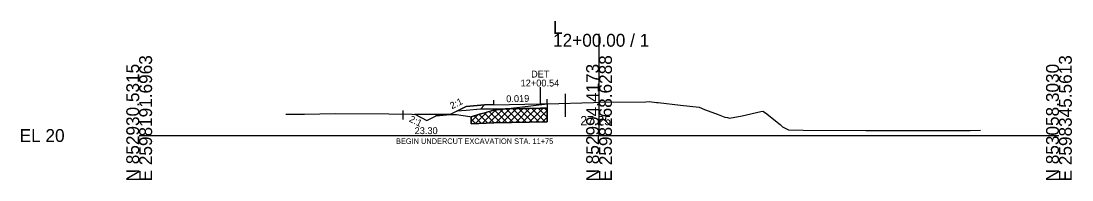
# Model space of a CAD drawing. Extents: x -26 to 1203, y -10 to 9526.
# Drawn here: x -25.7 to 202.8, y 1990.3 to 2024.9 of the extents above; entities that cross this region are included whole.
import ezdxf

# ---------------------------------------------------------------- set-up
doc = ezdxf.new("R2010")
doc.units = 0
for name, color, linetype in [('Exist Cross Section Cell', 7, 'Continuous'), ('Exist XS Center Line Elevation Label', 7, 'Continuous'), ('Exist XS Ground Line', 7, 'Continuous'), ('Prop XS Alignment Label', 7, 'Continuous'), ('Prop XS DDE', 7, 'Continuous'), ('Prop XS DDE Earthwork Shape', 7, 'Continuous'), ('Prop XS DDE Elevations', 7, 'Continuous'), ('Prop XS DDE Slope Text', 7, 'Continuous'), ('Prop XS Earthwork Shape', 7, 'Continuous'), ('Prop XS EOT Tick Mark', 7, 'Continuous'), ('Prop XS Exc Vertical Line 1', 7, 'Continuous'), ('Prop XS Exc Vertical Line 2', 7, 'Continuous'), ('Prop XS Finish Grade', 7, 'Continuous'), ('Prop XS Finish Grade Earthwork', 7, 'Continuous'), ('Prop XS Finish Grade Paved Shoulder', 7, 'Continuous'), ('Prop XS Finish Grade Pavement', 7, 'Continuous'), ('Prop XS Pvmt Edge Slope', 7, 'Continuous'), ('Prop XS SE Text', 7, 'Continuous'), ('Prop XS Side Slope Text', 7, 'Continuous'), ('Prop XS Station Labels', 7, 'Continuous'), ('Prop XS Subgrade Earthwork', 7, 'Continuous'), ('Prop XS Undercut Exc', 7, 'Continuous'), ('Prop XS Undercut Exc Hatch', 7, 'Continuous'), ('Scratch_Level_1', 7, 'Continuous')]:
    doc.layers.add(name, color=color, linetype=linetype)

msp = doc.modelspace()

# ---------------------------------------------------------------- linework, layer by layer
at = {"layer": 'Exist Cross Section Cell'}
for p, q in [((100, 2000), (100, 2022.14)), ((0, 2000), (100, 2000)), ((100, 2000), (200, 2000))]:
    msp.add_line(p, q, dxfattribs=at)
at = {"layer": 'Exist XS Ground Line'}
for p, q in [((82.76, 2006.18), (88.75, 2006.89)), ((88.75, 2006.89), (98.76, 2007.21)), ((98.76, 2007.21), (99.98, 2007.25)), ((99.98, 2007.25), (110.19, 2007.37)), ((110.19, 2007.37), (110.9, 2007.38)), ((110.9, 2007.38), (112.47, 2007.2)), ((112.47, 2007.2), (112.87, 2007.16)), ((112.87, 2007.16), (117.69, 2006.61)), ((117.69, 2006.61), (121.76, 2006.17)), ((31.91, 2004.63), (35.95, 2004.65)), ((35.95, 2004.65), (42.59, 2004.77)), ((42.59, 2004.77), (54.3, 2004.72)), ((54.3, 2004.72), (64.41, 2004.55)), ((64.41, 2004.55), (69.02, 2004.57)), ((69.02, 2004.57), (71.87, 2004.17)), ((72.18, 2004.08), (73.97, 2004.63)), ((73.97, 2004.63), (77.13, 2005.54)), ((77.13, 2005.54), (82.76, 2006.18)), ((121.76, 2006.17), (122.95, 2005.69)), ((122.95, 2005.69), (125.9, 2004.58)), ((125.9, 2004.58), (127.34, 2004)), ((128.39, 2003.8), (131.09, 2004.31)), ((131.09, 2004.31), (135.19, 2005.23)), ((135.19, 2005.23), (135.64, 2005.33)), ((135.64, 2005.33), (136.16, 2004.95)), ((136.16, 2004.95), (139.36, 2002.43)), ((71.87, 2004.17), (72.18, 2004.08)), ((127.34, 2004), (127.95, 2003.89)), ((127.95, 2003.89), (128.39, 2003.8)), ((139.36, 2002.43), (139.92, 2001.92)), ((139.92, 2001.92), (141.17, 2001.22)), ((141.17, 2001.22), (144.39, 2001.19)), ((144.39, 2001.19), (157.99, 2001.06)), ((157.99, 2001.06), (180.68, 2001.12)), ((180.68, 2001.12), (182.96, 2001.14))]:
    msp.add_line(p, q, dxfattribs=at)
at = {"layer": 'Prop XS DDE'}
for p, q in [((59.91, 2004.63), (62.56, 2003.3)), ((62.56, 2003.3), (64.59, 2004.31)), ((64.59, 2004.31), (67.59, 2004.56))]:
    msp.add_line(p, q, dxfattribs=at)
at = {"layer": 'Prop XS DDE Earthwork Shape'}
for p, q in [((64.41, 2004.55), (59.91, 2004.63)), ((59.91, 2004.63), (62.56, 2003.3)), ((62.56, 2003.3), (64.59, 2004.31)), ((67.59, 2004.56), (64.41, 2004.55)), ((64.59, 2004.31), (67.59, 2004.56))]:
    msp.add_line(p, q, dxfattribs=at)
at = {"layer": 'Prop XS Earthwork Shape'}
for points in [[(79.55, 2005.82), (82.76, 2006.18), (88.71, 2006.88), (88.71, 2005.99), (87.26, 2005.96)], [(67.59, 2004.56), (69.02, 2004.57), (71.87, 2004.17), (72.18, 2004.08), (73.97, 2004.63), (77.13, 2005.54), (79.55, 2005.82), (77.12, 2005.77), (75.12, 2005.73), (74.19, 2005.71), (71.12, 2005.47), (69.08, 2005.31)], [(87.26, 2005.96), (88.71, 2005.99), (88.71, 2002.99), (77.12, 2002.77), (72.18, 2002.55), (72.18, 2004.08), (73.97, 2004.63), (77.13, 2005.54), (79.55, 2005.82)]]:
    msp.add_lwpolyline(points, close=True, dxfattribs=at)
at = {"layer": 'Prop XS EOT Tick Mark'}
for p, q in [((77.12, 2006.69), (77.12, 2007.69)), ((88.71, 2006.91), (88.71, 2007.91))]:
    msp.add_line(p, q, dxfattribs=at)
at = {"layer": 'Prop XS Exc Vertical Line 1'}
msp.add_line((57.35, 2005.47), (57.35, 2003.47), dxfattribs=at)
at = {"layer": 'Prop XS Exc Vertical Line 2'}
msp.add_line((92.62, 2009.06), (92.62, 2004.07), dxfattribs=at)
at = {"layer": 'Prop XS Finish Grade'}
for p, q in [((75.12, 2006.65), (71.12, 2006.33)), ((71.12, 2006.33), (69.08, 2005.31))]:
    msp.add_line(p, q, dxfattribs=at)
at = {"layer": 'Prop XS Finish Grade Earthwork'}
msp.add_line((69.08, 2005.31), (67.59, 2004.56), dxfattribs=at)
at = {"layer": 'Prop XS Finish Grade Paved Shoulder'}
msp.add_line((77.12, 2006.69), (75.12, 2006.65), dxfattribs=at)
at = {"layer": 'Prop XS Finish Grade Pavement'}
for p, q in [((77.12, 2006.69), (87.26, 2006.88)), ((87.26, 2006.88), (88.71, 2006.91))]:
    msp.add_line(p, q, dxfattribs=at)
at = {"layer": 'Prop XS Pvmt Edge Slope'}
msp.add_line((75.12, 2006.65), (74.19, 2005.71), dxfattribs=at)
at = {"layer": 'Prop XS Side Slope Text'}
msp.add_line((87.26, 2006.88), (87.26, 2010.53), dxfattribs=at)
at = {"layer": 'Prop XS Subgrade Earthwork'}
for p, q in [((88.71, 2006.88), (88.71, 2005.99)), ((71.12, 2005.47), (69.08, 2005.31)), ((74.19, 2005.71), (71.12, 2005.47)), ((75.12, 2005.73), (74.19, 2005.71)), ((77.12, 2005.77), (75.12, 2005.73)), ((87.26, 2005.96), (77.12, 2005.77))]:
    msp.add_line(p, q, dxfattribs=at)
at = {"layer": 'Prop XS Undercut Exc'}
for p, q in [((79.55, 2005.82), (88.71, 2005.99)), ((88.71, 2005.99), (88.71, 2002.99)), ((72.18, 2002.55), (72.18, 2004.08)), ((77.12, 2002.77), (72.18, 2002.55)), ((88.71, 2002.99), (77.12, 2002.77))]:
    msp.add_line(p, q, dxfattribs=at)
at = {"layer": 'Prop XS Undercut Exc Hatch'}
for p, q in [((72.17, 2003.03), (73.68, 2004.54)), ((72.84, 2004.28), (74.47, 2002.65)), ((73.15, 2002.6), (75.67, 2005.12)), ((73.93, 2004.61), (75.83, 2002.71)), ((74.63, 2002.66), (77.56, 2005.59)), ((75.02, 2004.93), (77.18, 2002.77)), ((76.11, 2002.73), (79.15, 2005.77)), ((76.12, 2005.25), (78.57, 2002.8)), ((77.23, 2005.55), (79.96, 2002.82)), ((77.57, 2002.78), (80.63, 2005.84)), ((78.5, 2005.7), (81.34, 2002.85)), ((79.02, 2002.81), (82.08, 2005.86)), ((79.79, 2005.82), (82.73, 2002.88)), ((80.46, 2002.83), (83.52, 2005.89)), ((81.18, 2005.85), (84.12, 2002.9)), ((81.9, 2002.86), (84.96, 2005.92)), ((82.56, 2005.87), (85.51, 2002.93)), ((83.34, 2002.89), (86.4, 2005.95)), ((83.95, 2005.9), (86.89, 2002.96)), ((84.78, 2002.92), (87.84, 2005.98)), ((85.34, 2005.93), (88.28, 2002.98)), ((86.23, 2002.94), (88.71, 2005.43)), ((86.73, 2005.95), (88.71, 2003.97)), ((88.11, 2005.98), (88.71, 2005.38)), ((72.17, 2003.54), (73.12, 2002.59)), ((87.67, 2002.97), (88.71, 2004.02))]:
    msp.add_line(p, q, dxfattribs=at)
msp.add_lwpolyline([(72.18, 2002.55), (77.12, 2002.77), (88.71, 2002.99), (88.71, 2005.99), (79.55, 2005.82), (77.13, 2005.54), (74.93, 2004.9), (73.97, 2004.63), (72.18, 2004.08)], close=True, dxfattribs=at)
at = {"layer": 'Scratch_Level_1'}
msp.add_lwpolyline([(74.19, 2005.71), (71.12, 2005.47), (69.08, 2005.31), (71.12, 2006.33), (75.12, 2006.65)], close=True, dxfattribs=at)

# ---------------------------------------------------------------- texts
at = {"layer": 'Exist Cross Section Cell'}
for s, p in [('L', (90, 2022.14)), ('12+00.00 / 1', (90, 2019.34)), ('EL 20', (-26, 1998.6))]:
    msp.add_text(s, height=2.8, dxfattribs=at).set_placement(p)
for s, p in [('E 2598191.6963', (2.8, 1990)), ('E 2598268.6288', (102.8, 1990)), ('E 2598345.5613', (202.8, 1990)), ('N 852930.5315', (0, 1990)), ('N 852994.4173', (100, 1990)), ('N 853058.3030', (200, 1990))]:
    msp.add_text(s, height=2.8, rotation=90, dxfattribs=at).set_placement(p)
at = {"layer": 'Exist XS Center Line Elevation Label'}
msp.add_text('27.25', height=2, dxfattribs=at).set_placement((95.93, 2002.25))
at = {"layer": 'Prop XS Alignment Label'}
msp.add_text('DET', height=1.5, dxfattribs=at).set_placement((85.22, 2012.63))
at = {"layer": 'Prop XS DDE Elevations'}
msp.add_text('23.30', height=1.5, rotation=360, dxfattribs=at).set_placement((59.89, 2000.3))
at = {"layer": 'Prop XS DDE Slope Text'}
msp.add_text('2:1', height=1.5, rotation=333.4349, dxfattribs=at).set_placement((58.57, 2003.11))
at = {"layer": 'Prop XS SE Text'}
msp.add_text('0.019', height=1.5, rotation=1.1013, dxfattribs=at).set_placement((79.83, 2007.24))
at = {"layer": 'Prop XS Side Slope Text'}
msp.add_text('2:1', height=1.5, rotation=26.5651, dxfattribs=at).set_placement((68.02, 2005.69))
at = {"layer": 'Prop XS Station Labels'}
msp.add_text('12+00.54', height=1.5, dxfattribs=at).set_placement((82.94, 2010.68))
at = {"layer": 'Prop XS Undercut Exc Hatch'}
msp.add_text('BEGIN UNDERCUT EXCAVATION STA. 11+75', height=1.2, dxfattribs=at).set_placement((55.85, 1998.17))

doc.saveas('drawing.dxf')
